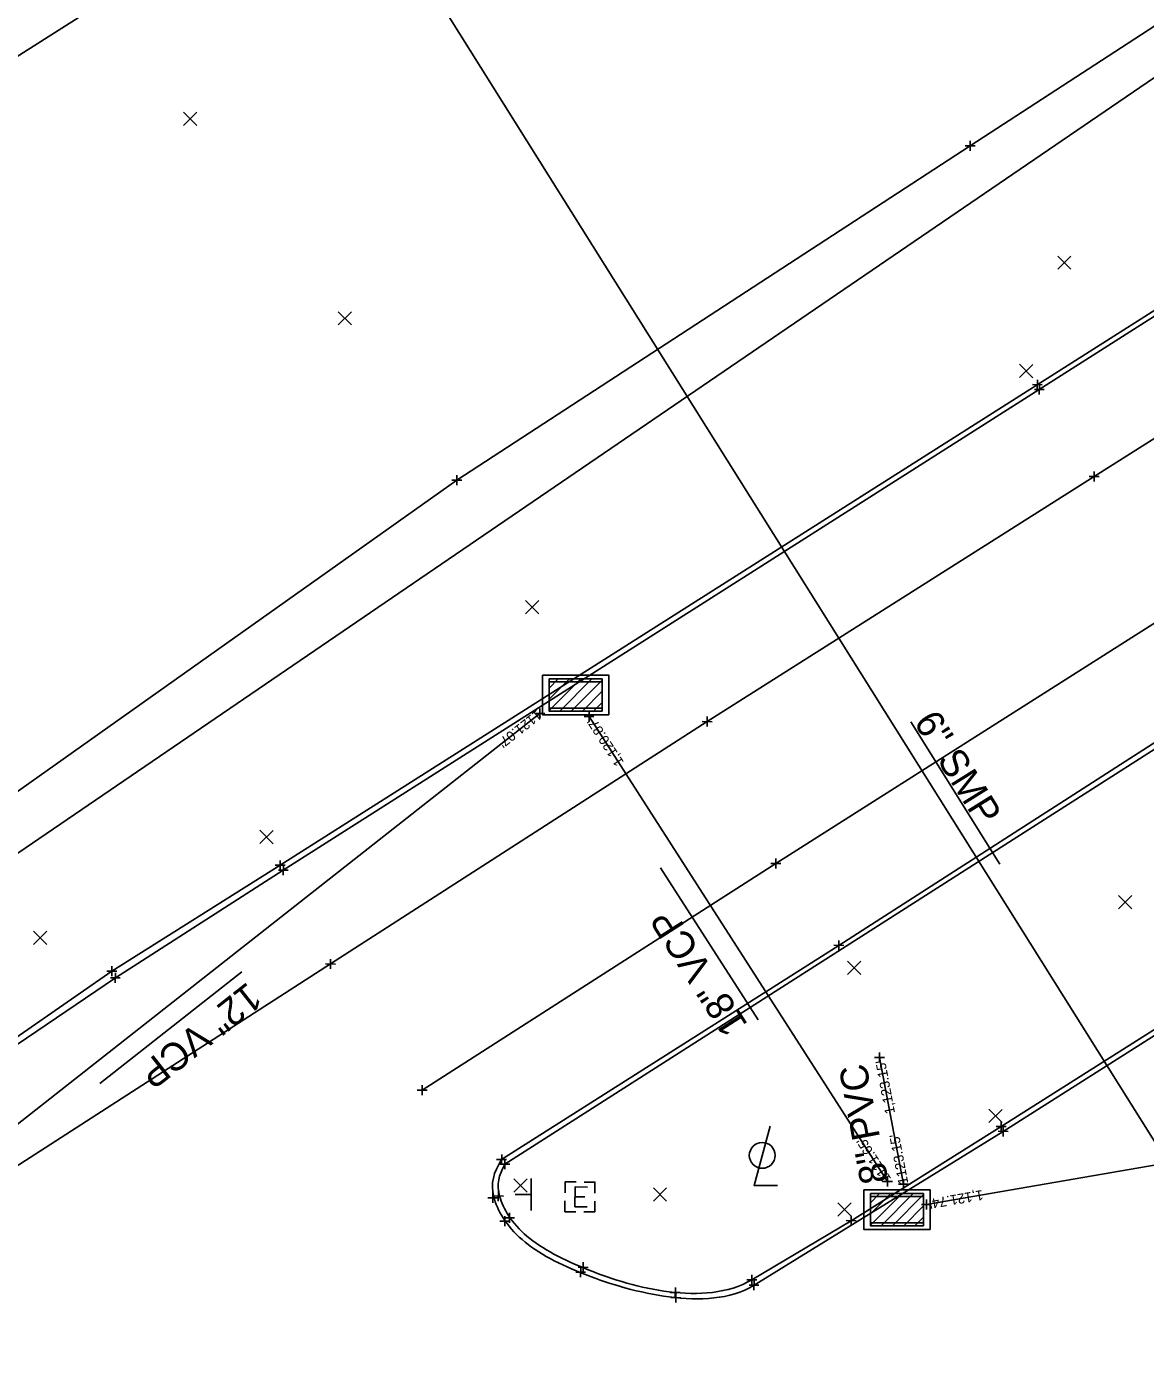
# Model space of a CAD drawing. Extents: x 142461 to 147261, y 511126 to 514697.
# Drawn here: x 144940.1 to 145052.6, y 512974.3 to 513109.1 of the extents above; entities that cross this region are included whole.
import ezdxf

# ---------------------------------------------------------------- set-up
doc = ezdxf.new("R2010")
doc.units = 0
for name, color, linetype in [('DR_X_Cells', 7, 'Continuous'), ('DR_X_Elev_Flow', 7, 'Continuous'), ('DR_X_Storm_Sewer', 7, 'Continuous'), ('DR_X_Text', 7, 'Continuous'), ('GK_Drainage_Nodes', 7, 'Continuous'), ('LT_X_Poles', 7, 'Continuous'), ('PM_X_Surveyed_Line', 7, 'Continuous'), ('PV_X_Curb', 7, 'Continuous'), ('PV_X_EOP', 7, 'Continuous'), ('SC_Scratch1', 7, 'Continuous'), ('SN_X_Public', 7, 'Continuous'), ('SV_X_Random_Point', 7, 'Continuous'), ('SV_X_Shot_Marker', 7, 'Continuous'), ('SV_X_Toe_of_Slope', 7, 'Continuous'), ('UT_X_Electric_Cells', 7, 'Continuous'), ('UT_X_Sanitary_Line', 7, 'Continuous'), ('UT_X_Sanitary_Text', 7, 'Continuous')]:
    doc.layers.add(name, color=color, linetype=linetype)

msp = doc.modelspace()

# ---------------------------------------------------------------- linework, layer by layer
at = {"layer": 'DR_X_Cells'}
for p, q in [((144992.63, 513040.34), (144995.82, 513043.52)), ((144992.63, 513041.47), (144994.68, 513043.52)), ((144992.63, 513042.6), (144993.55, 513043.52)), ((144993.72, 513040.29), (144996.95, 513043.52)), ((144994.85, 513040.29), (144997.97, 513043.41)), ((144995.98, 513040.29), (144997.97, 513042.28)), ((144997.11, 513040.29), (144997.97, 513041.15)), ((145024.94, 512988.6), (145028.13, 512991.78)), ((145024.94, 512989.73), (145027, 512991.78)), ((145024.94, 512990.86), (145025.86, 512991.78)), ((145026.03, 512988.55), (145029.26, 512991.78)), ((145027.16, 512988.55), (145030.28, 512991.67)), ((145028.29, 512988.55), (145030.28, 512990.54)), ((145029.42, 512988.55), (145030.28, 512989.41))]:
    msp.add_line(p, q, dxfattribs=at)
for points in [[(144991.97, 513043.91), (144998.63, 513043.91), (144998.63, 513039.91), (144991.97, 513039.91)], [(144992.63, 513043.52), (144997.97, 513043.52), (144997.97, 513040.29), (144992.63, 513040.29)], [(144992.63, 513043.24), (144997.97, 513043.24), (144997.97, 513040.57), (144992.63, 513040.57)], [(145024.28, 512992.17), (145030.94, 512992.17), (145030.94, 512988.17), (145024.28, 512988.17)], [(145024.94, 512991.78), (145030.28, 512991.78), (145030.28, 512988.55), (145024.94, 512988.55)], [(145024.94, 512991.5), (145030.28, 512991.5), (145030.28, 512988.84), (145024.94, 512988.84)]]:
    msp.add_lwpolyline(points, close=True, dxfattribs=at)
at = {"layer": 'DR_X_Elev_Flow'}
for p, q in [((144991.72, 513040.56), (144991.72, 513039.56)), ((144991.22, 513040.06), (144992.22, 513040.06)), ((144991.72, 513040.06), (144991.72, 513040.06)), ((144996.15, 513039.75), (144997.15, 513039.75)), ((144996.65, 513040.25), (144996.65, 513039.25)), ((144996.65, 513039.75), (144996.65, 513039.75)), ((145025.87, 513005.97), (145025.87, 513004.97)), ((145025.37, 513005.47), (145026.37, 513005.47)), ((145025.87, 513005.47), (145025.87, 513005.47)), ((145026.65, 512993.5), (145026.65, 512992.5)), ((145026.15, 512993), (145027.15, 512993)), ((145026.65, 512993), (145026.65, 512993)), ((145027.77, 512992.73), (145028.77, 512992.73)), ((145028.27, 512993.23), (145028.27, 512992.23)), ((145028.27, 512992.73), (145028.27, 512992.73)), ((145030.57, 512991.18), (145030.57, 512990.18)), ((145030.07, 512990.68), (145031.07, 512990.68)), ((145030.57, 512990.68), (145030.57, 512990.68))]:
    msp.add_line(p, q, dxfattribs=at)
at = {"layer": 'DR_X_Storm_Sewer'}
for p, q in [((145313.55, 513281.39), (144904.71, 513002.46)), ((144991.72, 513040.06), (144918.28, 512982.32)), ((145026.65, 512993), (144996.65, 513039.75)), ((145191.29, 513018.34), (145030.57, 512990.68)), ((145028.27, 512992.73), (145025.87, 513005.47))]:
    msp.add_line(p, q, dxfattribs=at)
at = {"layer": 'DR_X_Text'}
for p, q in [((145037.96, 513024.91), (145029, 513039.2)), ((145003.85, 513024.54), (145013.67, 513009.25)), ((144947.46, 513002.85), (144961.74, 513014.08))]:
    msp.add_line(p, q, dxfattribs=at)
at = {"layer": 'GK_Drainage_Nodes'}
for p, q in [((144995.3, 513043.91), (144995.3, 513043.91)), ((144992.63, 513041.91), (144992.63, 513041.91)), ((144995.3, 513043.24), (144995.3, 513043.24)), ((144995.3, 513041.91), (144995.3, 513041.91)), ((144995.3, 513041.91), (144995.3, 513041.91)), ((144997.97, 513041.91), (144997.97, 513041.91)), ((144995.3, 513040.57), (144995.3, 513040.57)), ((144995.3, 513040.29), (144995.3, 513040.29)), ((144995.3, 513039.91), (144995.3, 513039.91)), ((145027.61, 512992.17), (145027.61, 512992.17)), ((145027.61, 512991.5), (145027.61, 512991.5)), ((145024.94, 512990.17), (145024.94, 512990.17)), ((145027.61, 512990.17), (145027.61, 512990.17)), ((145027.61, 512990.17), (145027.61, 512990.17)), ((145030.28, 512990.17), (145030.28, 512990.17)), ((145027.61, 512988.84), (145027.61, 512988.84)), ((145027.61, 512988.55), (145027.61, 512988.55)), ((145027.61, 512988.17), (145027.61, 512988.17))]:
    msp.add_line(p, q, dxfattribs=at)
at = {"layer": 'LT_X_Poles'}
msp.add_lwpolyline([(145014.88, 512998.57), (145013.25, 512992.6), (145015.61, 512992.58)], dxfattribs=at)
msp.add_circle((145014.07, 512995.62), 1.3, dxfattribs=at)
at = {"layer": 'PM_X_Surveyed_Line'}
for points in [[(144161.19, 512623.62), (144234.91, 512664.76), (144308.58, 512704.75), (144382.31, 512742.08), (144431.43, 512764.26), (144460.46, 512777.08), (144499.91, 512794.34), (144547.7, 512814.68), (144592.59, 512833.3), (144667.23, 512864.35), (144709.98, 512882.09), (144731.76, 512891.11), (144777.76, 512910.35), (144847.49, 512940.98), (144877.97, 512956.57), (144906.17, 512973.31), (144970.66, 513014.86), (145008.54, 513039.23), (145047.45, 513063.87), (145126.17, 513113.66), (145208.14, 513166.05), (145269.39, 513204.92)], [(144979.87, 513002.18), (145015.44, 513024.96), (145056.46, 513050.99), (145134.2, 513100.33), (145217.05, 513153.1), (145277.89, 513191.73), (145294.07, 513201.96)]]:
    msp.add_lwpolyline(points, dxfattribs=at)
at = {"layer": 'PV_X_Curb'}
for p, q in [((145057.05, 513038.71), (144988.2, 512994.75)), ((145038.09, 512998.53), (145070.55, 513019.1)), ((145023.01, 512989.05), (145038.09, 512998.53)), ((145013.02, 512983.12), (145023.01, 512989.05))]:
    msp.add_line(p, q, dxfattribs=at)
msp.add_lwpolyline([(144906.62, 512975.04), (144910.56, 512977.96), (144915.88, 512983.2), (144920.32, 512988.51), (144935.68, 513005.16), (144948.67, 513014.13), (144965.59, 513024.78), (145041.73, 513073.1), (145115.39, 513119.87), (145203.02, 513175.49), (145259.95, 513211.93), (145276.5, 513223.26), (145307.25, 513248.71)], dxfattribs=at)
msp.add_open_spline([(144988.2, 512994.75), (144987.56, 512993.62), (144987.11, 512991.76), (144989.77, 512987.31), (144996.24, 512984.01), (145004.59, 512981.39), (145010.65, 512981.71), (145013.02, 512983.12)], degree=3, dxfattribs=at)
at = {"layer": 'PV_X_EOP'}
for p, q in [((145021.77, 513016.73), (145056.84, 513039.25)), ((145070.88, 513018.67), (145038.29, 512998.03)), ((144987.86, 512995.21), (145021.77, 513016.73)), ((145038.29, 512998.03), (145013.24, 512982.56))]:
    msp.add_line(p, q, dxfattribs=at)
for points in [[(144423.14, 512777.38), (144529.59, 512845.63), (144635.07, 512912.79), (144699.77, 512953.97), (144801.25, 513018.67), (144857.84, 513054.39), (144918.27, 513092.86), (145002.41, 513146.27), (145077.85, 513194.39), (145164.32, 513249.25)], [(145308.5, 513249.32), (145276.87, 513222.85), (145260.3, 513211.35), (145203.28, 513174.99), (145115.75, 513119.59), (145041.93, 513072.6), (144965.91, 513024.3), (144949.02, 513013.46), (144936.1, 513004.72), (144920.88, 512988.16), (144917.39, 512983.57), (144918.93, 512982.03), (144917.24, 512980.52), (144915.69, 512981.95)]]:
    msp.add_lwpolyline(points, dxfattribs=at)
msp.add_open_spline([(145013.24, 512982.56), (145010.86, 512981.09), (145004.57, 512980.94), (144996, 512983.48), (144989.26, 512986.92), (144986.47, 512991.74), (144987.03, 512993.86), (144987.86, 512995.21)], degree=3, dxfattribs=at)
at = {"layer": 'SN_X_Public'}
for p, q in [((144990.84, 512993.28), (144990.84, 512990.08)), ((144990.84, 512991.68), (144989.24, 512991.68)), ((144990.84, 512991.68), (144990.84, 512991.68))]:
    msp.add_line(p, q, dxfattribs=at)
at = {"layer": 'SV_X_Random_Point'}
for p, q in [((144955.88, 513099.17), (144957.22, 513100.51)), ((144955.88, 513100.51), (144957.22, 513099.17)), ((145043.78, 513084.7), (145045.11, 513086.03)), ((145043.78, 513086.03), (145045.11, 513084.7)), ((144971.42, 513079.11), (144972.76, 513080.44)), ((144971.42, 513080.44), (144972.76, 513079.11)), ((145039.94, 513073.81), (145041.28, 513075.14)), ((145039.95, 513075.15), (145041.27, 513073.8)), ((144990.27, 513050.05), (144991.6, 513051.39)), ((144990.27, 513051.39), (144991.6, 513050.05)), ((144963.55, 513026.96), (144964.9, 513028.29)), ((144963.56, 513028.3), (144964.88, 513026.95)), ((145049.9, 513020.4), (145051.23, 513021.74)), ((145049.9, 513021.74), (145051.23, 513020.4)), ((144940.79, 513016.82), (144942.12, 513018.16)), ((144940.79, 513018.16), (144942.12, 513016.82)), ((145022.63, 513013.81), (145023.98, 513015.13)), ((145022.65, 513015.14), (145023.97, 513013.8)), ((145036.85, 512998.92), (145038.2, 513000.24)), ((145036.86, 513000.26), (145038.18, 512998.91)), ((144989.08, 512991.93), (144990.43, 512993.25)), ((144989.1, 512993.26), (144990.42, 512991.91)), ((145003.12, 512991.03), (145004.45, 512992.36)), ((145003.12, 512992.36), (145004.45, 512991.03)), ((145021.67, 512989.52), (145023.02, 512990.84)), ((145021.68, 512990.86), (145023, 512989.51))]:
    msp.add_line(p, q, dxfattribs=at)
at = {"layer": 'SV_X_Shot_Marker'}
for p, q in [((145034.97, 513097.6), (145034.97, 513096.6)), ((145034.47, 513097.1), (145035.47, 513097.1)), ((145034.97, 513097.1), (145034.97, 513097.1)), ((145041.23, 513073.11), (145042.23, 513073.1)), ((145041.74, 513073.6), (145041.73, 513072.6)), ((145041.73, 513073.1), (145041.73, 513073.1)), ((145041.94, 513073.1), (145041.93, 513072.1)), ((145041.43, 513072.61), (145042.43, 513072.6)), ((145041.93, 513072.6), (145041.93, 513072.6)), ((144982.86, 513063.49), (144983.86, 513063.49)), ((144983.36, 513063.99), (144983.36, 513062.99)), ((144983.36, 513063.49), (144983.36, 513063.49)), ((145046.95, 513063.88), (145047.95, 513063.87)), ((145047.46, 513064.37), (145047.45, 513063.37)), ((145047.45, 513063.87), (145047.45, 513063.87)), ((145008.04, 513039.23), (145009.04, 513039.22)), ((145008.54, 513039.73), (145008.53, 513038.73)), ((145008.54, 513039.23), (145008.54, 513039.23)), ((144965.09, 513024.79), (144966.09, 513024.78)), ((144965.6, 513025.28), (144965.59, 513024.28)), ((144965.59, 513024.78), (144965.59, 513024.78)), ((144965.92, 513024.8), (144965.91, 513023.8)), ((145014.94, 513024.96), (145015.94, 513024.95)), ((145015.45, 513025.46), (145015.44, 513024.46)), ((145015.44, 513024.96), (145015.44, 513024.96)), ((144965.41, 513024.3), (144966.41, 513024.29)), ((144965.91, 513024.3), (144965.91, 513024.3)), ((145021.27, 513016.74), (145022.27, 513016.73)), ((145021.77, 513017.23), (145021.76, 513016.23)), ((145021.77, 513016.73), (145021.77, 513016.73)), ((144970.66, 513015.36), (144970.65, 513014.36)), ((144948.17, 513014.14), (144949.17, 513014.13)), ((144948.67, 513014.63), (144948.66, 513013.63)), ((144948.67, 513014.13), (144948.67, 513014.13)), ((144949.02, 513013.96), (144949.01, 513012.97)), ((144970.16, 513014.86), (144971.16, 513014.85)), ((144970.66, 513014.86), (144970.66, 513014.86)), ((144948.52, 513013.47), (144949.52, 513013.46)), ((144949.02, 513013.46), (144949.02, 513013.46)), ((144979.37, 513002.19), (144980.37, 513002.18)), ((144979.87, 513002.68), (144979.86, 513001.68)), ((144979.87, 513002.18), (144979.87, 513002.18)), ((145038.09, 512999.03), (145038.08, 512998.03)), ((145037.59, 512998.53), (145038.59, 512998.52)), ((145037.79, 512998.04), (145038.79, 512998.03)), ((145038.09, 512998.53), (145038.09, 512998.53)), ((145038.29, 512998.53), (145038.28, 512997.53)), ((145038.29, 512998.03), (145038.29, 512998.03)), ((144987.36, 512995.21), (144988.36, 512995.2)), ((144987.7, 512994.75), (144988.7, 512994.74)), ((144987.87, 512995.71), (144987.86, 512994.71)), ((144987.86, 512995.21), (144987.86, 512995.21)), ((144988.2, 512995.25), (144988.19, 512994.25)), ((144988.2, 512994.75), (144988.2, 512994.75)), ((144986.48, 512991.36), (144987.48, 512991.35)), ((144986.98, 512991.85), (144986.97, 512990.85)), ((144986.98, 512991.35), (144986.98, 512991.35)), ((144987.04, 512991.54), (144988.04, 512991.52)), ((144987.54, 512992.03), (144987.53, 512991.03)), ((144987.54, 512991.53), (144987.54, 512991.53)), ((144988.18, 512989.51), (144988.17, 512988.51)), ((144988.17, 512989.35), (144989.17, 512989.34)), ((144988.67, 512989.85), (144988.66, 512988.85)), ((144988.67, 512989.35), (144988.67, 512989.35)), ((145023.01, 512989.55), (145023, 512988.55)), ((144987.68, 512989.02), (144988.68, 512989.01)), ((144988.18, 512989.01), (144988.18, 512989.01)), ((145022.51, 512989.06), (145023.51, 512989.05)), ((145023.01, 512989.05), (145023.01, 512989.05)), ((144995.56, 512984.37), (144996.56, 512984.36)), ((144995.82, 512984.38), (144995.81, 512983.38)), ((144996.07, 512984.87), (144996.06, 512983.87)), ((144996.06, 512984.37), (144996.06, 512984.37)), ((144995.31, 512983.88), (144996.31, 512983.87)), ((144995.81, 512983.88), (144995.81, 512983.88)), ((145012.52, 512983.12), (145013.52, 512983.11)), ((145013.02, 512983.62), (145013.01, 512982.62)), ((145013.02, 512983.12), (145013.02, 512983.12)), ((145013.24, 512983.06), (145013.23, 512982.06)), ((145004.82, 512981.84), (145005.82, 512981.83)), ((145004.88, 512981.32), (145005.88, 512981.31)), ((145005.33, 512982.34), (145005.32, 512981.34)), ((145005.32, 512981.84), (145005.32, 512981.84)), ((145005.39, 512981.82), (145005.38, 512980.82)), ((145005.38, 512981.32), (145005.38, 512981.32)), ((145012.74, 512982.57), (145013.74, 512982.56)), ((145013.24, 512982.56), (145013.24, 512982.56))]:
    msp.add_line(p, q, dxfattribs=at)
at = {"layer": 'SV_X_Toe_of_Slope'}
msp.add_lwpolyline([(145536.33, 513468.51), (145487.34, 513431.87), (145445.96, 513398.71), (145400.54, 513359.53), (145354.59, 513321.64), (145305.79, 513280.24), (145266.24, 513246.77), (145228.58, 513220.65), (145175.08, 513189.66), (145126.31, 513155.94), (145081.98, 513127.67), (145034.97, 513097.1), (144983.36, 513063.49), (144934.41, 513028.84), (144889.77, 512994.77), (144833.63, 512962.42), (144772.97, 512934.59), (144716.73, 512910.04), (144663.56, 512886.77), (144614.86, 512866.63), (144547.92, 512838.93)], dxfattribs=at)
at = {"layer": 'UT_X_Electric_Cells'}
for p, q in [((144995.24, 512991.45), (144996.24, 512991.44)), ((144995.74, 512991.45), (144995.74, 512991.45))]:
    msp.add_line(p, q, dxfattribs=at)
for points in [[(144995.35, 512992.95), (144994.25, 512992.96), (144994.24, 512991.86)], [(144996.5, 512992.44), (144995.25, 512992.45), (144995.23, 512990.45), (144996.48, 512990.44)], [(144997.24, 512991.83), (144997.25, 512992.93), (144996.15, 512992.94)], [(144994.23, 512991.06), (144994.22, 512989.96), (144995.32, 512989.95)], [(144996.12, 512989.94), (144997.22, 512989.93), (144997.23, 512991.03)]]:
    msp.add_lwpolyline(points, dxfattribs=at)
at = {"layer": 'UT_X_Sanitary_Line'}
msp.add_line((144979.11, 513115.64), (145082.93, 512950.11), dxfattribs=at)
at = {"layer": 'UT_X_Sanitary_Text'}
msp.add_line((145037.96, 513024.91), (145029, 513039.2), dxfattribs=at)
msp.add_line((145037.96, 513024.91), (145029, 513039.2), dxfattribs=at)

# ---------------------------------------------------------------- texts
at = {"layer": 'DR_X_Text'}
for s, rotation, p in [('18" VCP', 122.6994, (145012.68, 513008.75)), ('12" VCP', 218.1794, (144962.33, 513013.14)), ('8" PVC', 100.6469, (145026.75, 512993.04))]:
    msp.add_text(s, height=2.8, rotation=rotation, dxfattribs=at).set_placement(p)
at = {"layer": 'SC_Scratch1'}
for s, rotation, p in [("1121.07'", 218.1794, (144991.41, 513040.46)), ("1,120.87'", 122.6994, (145000.19, 513035.15)), ("1,123.15'", 100.6469, (145027.43, 512999.88)), ("1123.15'", 100.6469, (145028.76, 512992.82)), ("1121.65'", 122.6994, (145027.07, 512993.27)), ("1,121.74'", 189.7645, (145036.19, 512992.15))]:
    msp.add_text(s, height=1, rotation=rotation, dxfattribs=at).set_placement(p)
at = {"layer": 'UT_X_Sanitary_Text'}
msp.add_text('6" SMP', height=2.8, rotation=301.9347, dxfattribs=at).set_placement((145029.24, 513039.18))

doc.saveas('drawing.dxf')
